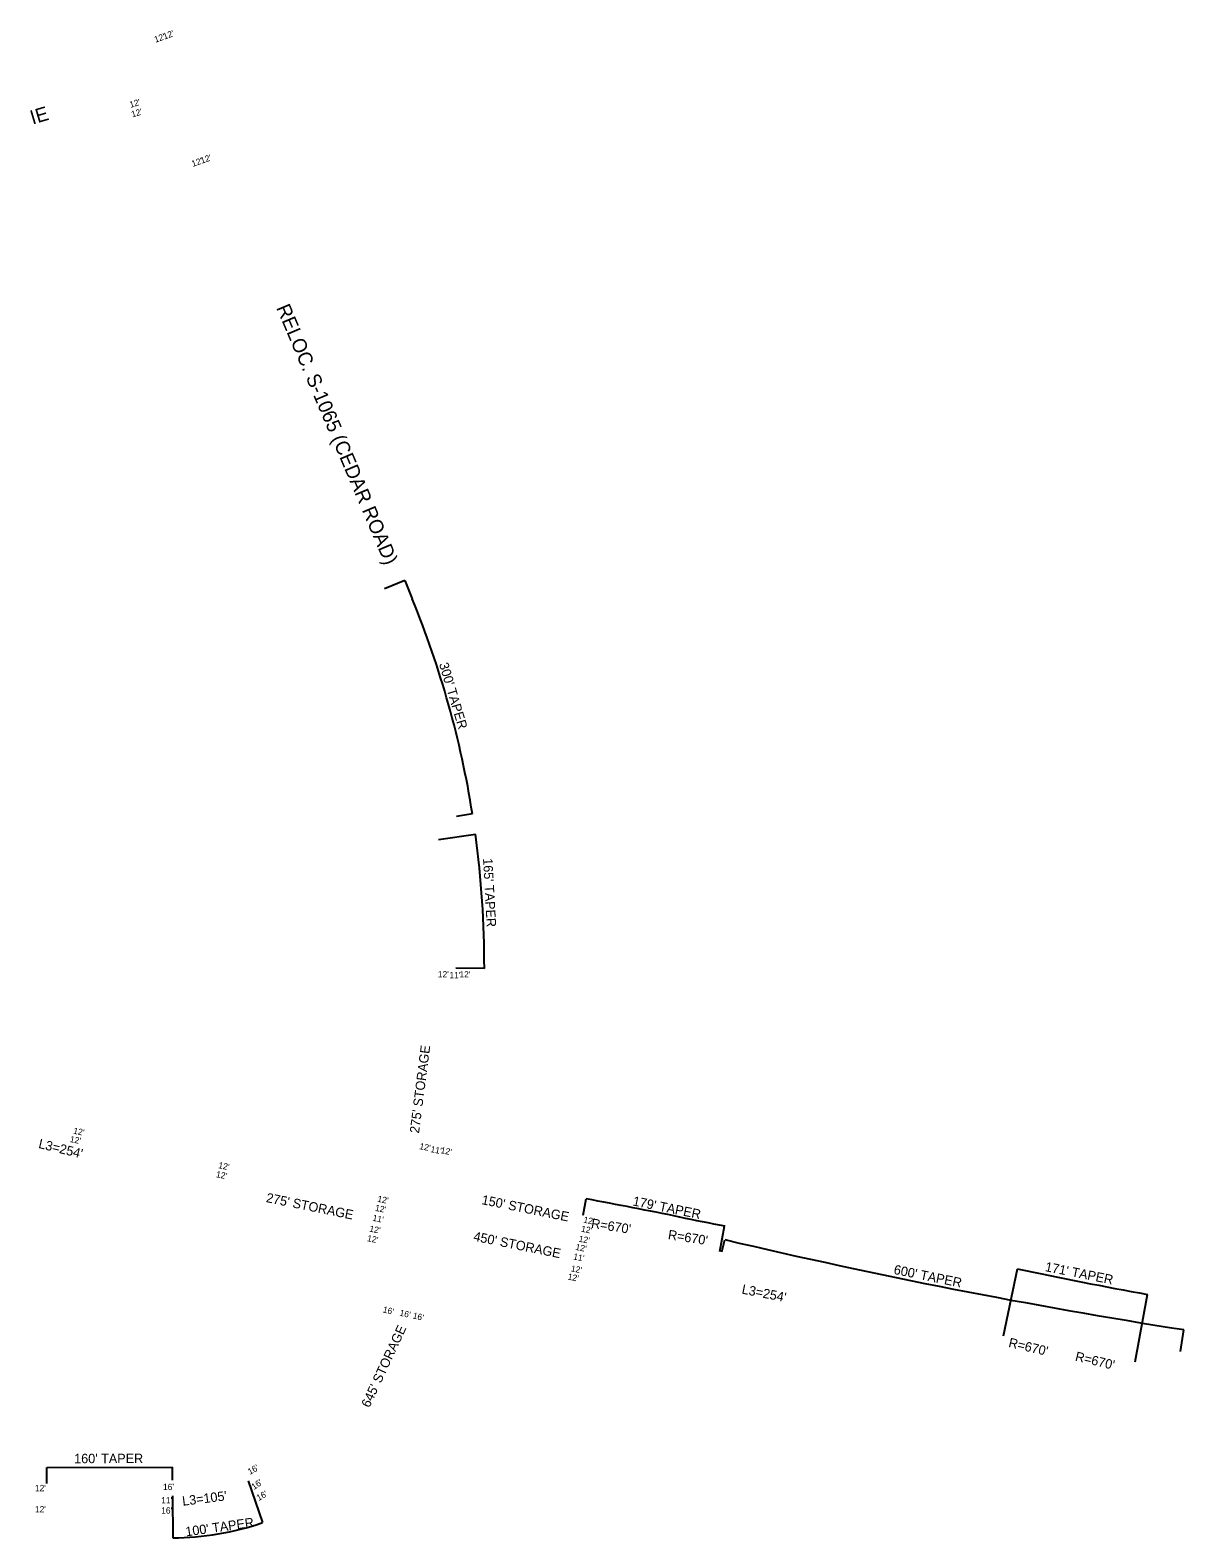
# Model space of a CAD drawing. Extents: x 1938444 to 1943914, y 779364 to 784498.
# Drawn here: x 1942445 to 1943914, y 779722 to 781642 of the extents above; entities that cross this region are included whole.
import ezdxf

# ---------------------------------------------------------------- set-up
doc = ezdxf.new("R2010")
doc.units = 0
doc.layers.add('RD_PD_Final_TX', color=7, linetype='Continuous')
doc.layers.add('RD_TX_RoadID', color=7, linetype='Continuous')

msp = doc.modelspace()

# ---------------------------------------------------------------- linework, layer by layer
at = {"layer": 'RD_PD_Final_TX'}
for p, q in [((1942922.1, 780940.8), (1942896.2, 780930.2)), ((1942922.1, 780940.8), (1942931.5, 780917.7)), ((1943008.2, 780643.8), (1942987.9, 780640.6)), ((1943012, 780617.8), (1942965.1, 780610.8)), ((1943023.3, 780447.2), (1942986.8, 780447.3)), ((1943149.1, 780133.2), (1943153, 780153.8)), ((1943322.9, 780086.9), (1943329.2, 780119.2)), ((1943325.8, 780086.2), (1943329.5, 780101.8)), ((1943684.1, 779979.3), (1943701.8, 780064.5)), ((1943851.8, 779946.4), (1943867.6, 780032)), ((1943909.4, 779959.6), (1943913.7, 779987.2)), ((1942466.4, 779811.9), (1942626.4, 779812.2)), ((1942466.5, 779791.4), (1942466.4, 779811.9)), ((1942626.4, 779795.7), (1942626.4, 779812.2)), ((1942722.6, 779794.6), (1942741.1, 779741.7)), ((1942626.5, 779775.7), (1942626.6, 779722.2))]:
    msp.add_line(p, q, dxfattribs=at)
for centre, radius, start, end in [((1941793.3, 780451.4), 1230, 8.9988, 22.2776), ((1941793.3, 780451.4), 1230, 359.8026, 7.7767), ((1941691.3, 772342.9), 7946.5, 78.52844, 79.40043), ((1944821.7, 787768.5), 7793.5, 258.52844, 258.95962), ((1945123.5, 787703.5), 7810.5, 256.72143, 261.08959), ((1945281.3, 787677.9), 7775.5, 258.27909, 259.52402), ((1942625.9, 780072.2), 350, 270.1092, 289.2078)]:
    msp.add_arc(centre, radius, start, end, dxfattribs=at)

# ---------------------------------------------------------------- texts
for s, height, rotation, p in [("12'", 8, 19.5877, (1942604.7, 781625.5)), ("12'", 8, 19.5877, (1942616, 781629.5)), ("12'", 8, 16.654, (1942572.9, 781542.6)), ("12'", 8, 16.654, (1942575.2, 781530.4)), ("12'", 8, 19.5877, (1942652.3, 781467.4)), ("12'", 8, 19.5877, (1942663.6, 781471.4)), ("300' TAPER", 12, 286.6719, (1942965.5, 780834.6)), ("165' TAPER", 12, 273.1503, (1943021.6, 780587.1)), ("12'", 8, 359.7918, (1942964.1, 780435.7)), ("11'", 8, 359.7918, (1942978.8, 780434.6)), ("12'", 8, 359.7918, (1942991.6, 780435.6)), ("275' STORAGE", 12, 82.6751, (1942940.1, 780236.7)), ("12'", 8, 348.9016, (1942495.2, 780226.2)), ("12'", 8, 348.9016, (1942499.6, 780236.8)), ("L3=254'", 12, 346.2791, (1942455, 780218.7)), ("12'", 8, 348.9016, (1942940.2, 780217.2)), ("11'", 8, 348.9016, (1942954.3, 780213.4)), ("12'", 8, 348.9016, (1942967.2, 780212)), ("12'", 8, 348.9016, (1942684.2, 780192.9)), ("12'", 8, 348.9016, (1942681.3, 780181.4)), ("275' STORAGE", 12, 348.4993, (1942744.8, 780149.8)), ("12'", 8, 348.9016, (1942886.7, 780150.1)), ("150' STORAGE", 12, 348.6012, (1943019.2, 780147.1)), ("179' TAPER", 12, 348.4749, (1943211.5, 780145.5)), ("12'", 8, 348.9016, (1942883.7, 780138.6)), ("12'", 8, 348.9016, (1942876.5, 780112.2)), ("11'", 8, 348.9016, (1942880.5, 780125.9)), ("12'", 8, 348.9016, (1943146, 780112.1)), ("12'", 8, 348.9016, (1943149, 780123.6)), ("R=670'", 12, 351.2077, (1943158.7, 780117)), ("12'", 8, 348.9016, (1942873.6, 780100)), ("450' STORAGE", 12, 348.4993, (1943008.7, 780100.6)), ("12'", 8, 348.9016, (1943142.9, 780099.4)), ("R=670'", 12, 351.2077, (1943256.5, 780102.6)), ("11'", 8, 348.9016, (1943136, 780076.7)), ("12'", 8, 348.9016, (1943138.8, 780088.9)), ("12'", 8, 348.9016, (1943133, 780061.6)), ("600' TAPER", 12, 348.5029, (1943543.7, 780058.3)), ("171' TAPER", 12, 348.6859, (1943736.4, 780061.9)), ("12'", 8, 348.9016, (1943128.9, 780051.1)), ("L3=254'", 12, 348.8938, (1943350.3, 780033.3)), ("16'", 8, 346.1985, (1942893.5, 780009.4)), ("16'", 8, 346.9849, (1942914.8, 780005.2)), ("16'", 8, 346.5512, (1942931.6, 780001.7)), ("645' STORAGE", 12, 65.1534, (1942877, 779887.1)), ("R=670'", 12, 346.738, (1943689.8, 779965.4)), ("R=670'", 12, 346.738, (1943774.6, 779947.8)), ("160' TAPER", 12, 0.1092, (1942501.2, 779817.2)), ("16'", 8, 29.3418, (1942724.9, 779802.3)), ("12'", 8, 0.1092, (1942451.3, 779781.6)), ("16'", 8, 0.1092, (1942614.3, 779783)), ("16'", 8, 34.7104, (1942730.2, 779783)), ("11'", 8, 0.1092, (1942612, 779766)), ("L3=105'", 12, 7.0745, (1942639.5, 779763)), ("16'", 8, 29.3418, (1942736, 779769)), ("12'", 8, 0.1092, (1942451.3, 779754.7)), ("16'", 8, 0.1092, (1942612, 779753.1)), ("100' TAPER", 12, 8.0197, (1942643.7, 779724))]:
    msp.add_text(s, height=height, rotation=rotation, dxfattribs=at).set_placement(p)
at = {"layer": 'RD_TX_RoadID'}
for s, rotation, p in [('I', 16.654, (1942448.2, 781521.2)), ('E', 16.654, (1942454.8, 781523.2)), ('RELOC. S-1065 (CEDAR ROAD)', 292.9363, (1942758.2, 781288.2))]:
    msp.add_text(s, height=18, rotation=rotation, dxfattribs=at).set_placement(p)

doc.saveas('drawing.dxf')
